// Mitsubishi GX Works2 project: Weight 1   PLC: FX3U/FX3UC

PROGRAM MAIN
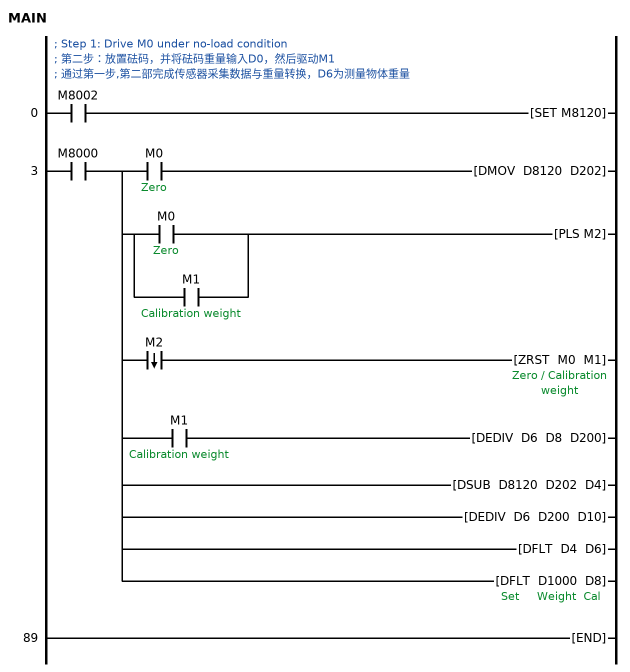
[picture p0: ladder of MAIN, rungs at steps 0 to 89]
; Step 1: Drive M0 under no-load condition
; 第二步：放置砝码，并将砝码重量输入D0，然后驱动M1
; 通过第一步,第二部完成传感器采集数据与重量转换，D6为测量物体重量
0     LD      M8002
      SET     M8120
3     LD      M8000
      MPS
      AND     M0  ; Zero
      DMOV    D8120 D202
      MRD
      LD      M0  ; Zero
      OR      M1  ; Calibration weight
      ANB
      PLS     M2
      MRD
      ANDF    M2
      ZRST    M0 M1
      MRD
      AND     M1  ; Calibration weight
      DEDIV   D6 D8 D200
      MPP
      DSUB    D8120 D202 D4
      DEDIV   D6 D200 D10
      DFLT    D4 D6
      DFLT    D1000 D8  ; Set     Weight  Cal
89    END
END_PROGRAM

// device comments not shown above
D0  ; weight  Cal
D2  ; display weight
